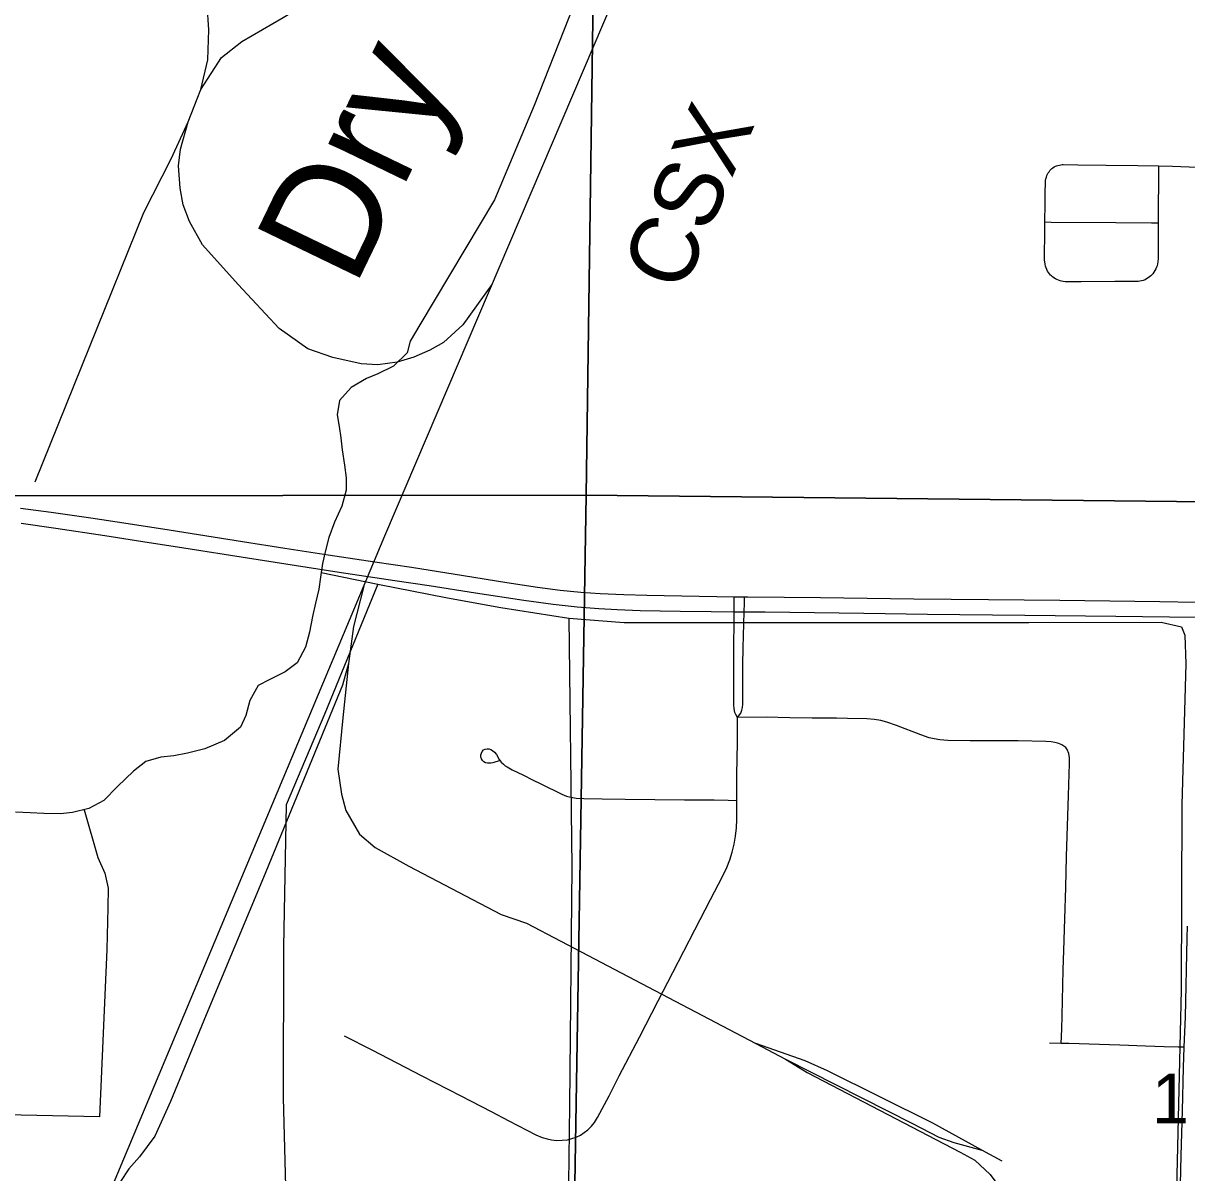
# Model space of a CAD drawing. Extents: x 0 to 34, y 0 to 22.
# Drawn here: x 7.043 to 8.019, y 17.308 to 18.272 of the extents above; entities that cross this region are included whole.
import ezdxf

# ---------------------------------------------------------------- set-up
doc = ezdxf.new("R2010")
doc.units = 0
for name, color, linetype in [('GM_X_Corporation', 7, 'Continuous'), ('GM_X_County_Road', 7, 'Continuous'), ('GM_X_Minor_River', 7, 'Continuous'), ('GM_X_Minor_River_Text', 7, 'Continuous'), ('GM_X_Rail_Line', 7, 'Continuous'), ('GM_X_Rail_Line_Text', 7, 'Continuous'), ('GM_X_Section_Text', 7, 'Continuous'), ('GM_X_State_Route', 7, 'Continuous'), ('GM_X_Township_Road', 7, 'Continuous')]:
    doc.layers.add(name, color=color, linetype=linetype)

msp = doc.modelspace()

# ---------------------------------------------------------------- linework, layer by layer
at = {"layer": 'GM_X_Corporation'}
for points in [[(6.50454, 18.87812), (7.00649, 18.89081), (7.52848, 18.83427), (7.51498, 17.8763), (6.49696, 17.87536)], [(7.52848, 18.83427), (8.56457, 18.82324), (8.56257, 18.42645), (8.55788, 17.86518), (7.51498, 17.8763)], [(6.49696, 17.87536), (7.51498, 17.8763), (7.49907, 16.90775), (6.47447, 16.92623)], [(7.51498, 17.8763), (8.55788, 17.86518), (8.55531, 17.77577), (8.50493, 17.42275), (8.49555, 16.88277), (7.49907, 16.90775)]]:
    msp.add_lwpolyline(points, close=True, dxfattribs=at)
at = {"layer": 'GM_X_County_Road'}
for points in [[(8.01675, 17.41339), (8.0177, 17.43885), (8.01916, 17.50487), (8.01949, 17.51487)], [(8.01278, 17.26906), (8.01322, 17.28589), (8.01417, 17.3225), (8.01539, 17.36001), (8.01612, 17.39628), (8.01675, 17.41339)]]:
    msp.add_lwpolyline(points, dxfattribs=at)
at = {"layer": 'GM_X_Minor_River'}
for points in [[(7.54054, 18.37809), (7.50431, 18.28675), (7.4715, 18.20327), (7.43799, 18.12398), (7.37544, 18.01924)], [(7.37544, 18.01924), (7.36733, 18.00567), (7.36494, 17.99583), (7.35346, 17.98459), (7.34015, 17.9783), (7.33066, 17.97425), (7.31772, 17.96682), (7.30813, 17.95593), (7.30609, 17.94381), (7.30785, 17.93392), (7.30924, 17.92441), (7.31024, 17.91453), (7.31235, 17.90159), (7.31372, 17.89095), (7.31359, 17.8807), (7.31001, 17.86708), (7.3038, 17.85387), (7.2991, 17.84102), (7.29592, 17.82892), (7.2939, 17.81907), (7.29225, 17.8077), (7.2906, 17.79748), (7.28781, 17.78574), (7.2854, 17.77477), (7.28296, 17.76151), (7.2794, 17.74903), (7.27243, 17.73583), (7.26251, 17.72836), (7.24958, 17.72169), (7.2397, 17.71688), (7.23273, 17.70406), (7.22955, 17.69158), (7.22489, 17.68176), (7.21152, 17.67054), (7.19519, 17.66354), (7.18041, 17.65993), (7.16905, 17.65779), (7.15808, 17.65679), (7.14557, 17.65315), (7.13526, 17.64493), (7.12188, 17.63219), (7.11039, 17.62019), (7.09784, 17.61351), (7.08419, 17.61027), (7.07398, 17.60926), (7.06001, 17.60943), (7.04868, 17.60996), (7.03622, 17.61049)], [(7.2928, 17.81154), (7.34015, 17.80179), (7.39855, 17.79043), (7.4434, 17.78227), (7.50033, 17.7732), (7.54675, 17.76959), (7.64421, 17.7695), (7.75679, 17.7696), (7.88636, 17.76949), (7.99744, 17.77), (8.01438, 17.76599), (8.01732, 17.75912), (8.01814, 17.73481), (8.01473, 17.61679), (8.01424, 17.46153), (8.0102, 17.29417), (8.00744, 17.10934), (7.99612, 16.90563), (7.99002, 16.78462)], [(7.34015, 17.80179), (7.29568, 17.6934), (7.26334, 17.61675), (7.26105, 17.49758), (7.26093, 17.3708), (7.26444, 17.23296)], [(7.50033, 17.7732), (7.50294, 17.56477), (7.50111, 17.36436), (7.4983, 17.1465), (7.49753, 16.99885)], [(7.09397, 17.61259), (7.10524, 17.57242), (7.11112, 17.55944), (7.11398, 17.54688), (7.11377, 17.53056), (7.11293, 17.49527), (7.10659, 17.3549), (6.98801, 17.35752), (6.98647, 17.23873), (6.98545, 17.0721), (6.98596, 16.9066), (6.98102, 16.72902), (6.9765, 16.58447), (6.96643, 16.36141)]]:
    msp.add_lwpolyline(points, dxfattribs=at)
at = {"layer": 'GM_X_Rail_Line'}
for p, q in [((7.65732, 17.4165), (7.68214, 17.40332)), ((7.86393, 17.3177), (7.84679, 17.32712))]:
    msp.add_line(p, q, dxfattribs=at)
for points in [[(7.19183, 18.21678), (7.19765, 18.24147), (7.19852, 18.26676), (7.19707, 18.28799), (7.19067, 18.30427), (7.17206, 18.33567), (7.16479, 18.35224), (7.15927, 18.37405), (7.1584, 18.39062), (7.15956, 18.4069), (7.16305, 18.41998), (7.1898, 18.48773), (7.30345, 18.7703), (7.71605, 19.7423), (7.73668, 19.78564), (7.75221, 19.80327), (7.77065, 19.81832), (7.78813, 19.82778), (7.80537, 19.83531), (7.8226, 19.83919), (7.85149, 19.8421), (7.89227, 19.84235), (7.93353, 19.84041), (7.9913, 19.8421)], [(5.77239, 14.1), (5.90233, 14.40655), (6.10798, 14.90116), (7.0925, 17.23709), (7.34619, 17.84225), (7.58257, 18.39702), (7.87412, 19.10843), (7.90221, 19.17079), (7.93383, 19.23755), (7.95841, 19.28147), (7.99266, 19.31836), (8.05237, 19.36024), (8.34578, 19.53684)], [(7.19183, 18.21678), (7.20904, 18.2434), (7.22605, 18.25694), (7.26075, 18.27707), (7.31351, 18.309), (7.35828, 18.33676), (7.3791, 18.35377), (7.39319, 18.37303), (7.42929, 18.44836), (7.72615, 19.20856)], [(7.18103, 18.18951), (7.18877, 18.20881), (7.19183, 18.21678)], [(7.05287, 17.8875), (7.14404, 18.11338), (7.16683, 18.15854), (7.18103, 18.18951)], [(7.43597, 18.05297), (7.41163, 18.01917), (7.39527, 18.00432), (7.38376, 17.99796), (7.37043, 17.99221), (7.35649, 17.98796), (7.34013, 17.98584), (7.3262, 17.98645), (7.30257, 17.9919), (7.28136, 17.99917), (7.25732, 18.01621), (7.22296, 18.05296), (7.19314, 18.08625), (7.1821, 18.10586), (7.17694, 18.12005), (7.17436, 18.13381), (7.17307, 18.15252), (7.17458, 18.16671), (7.18103, 18.18951)], [(7.32855, 17.80017), (7.31988, 17.76617), (7.31551, 17.73521)], [(7.31551, 17.73521), (7.31068, 17.71715), (7.24438, 17.55579), (7.19619, 17.44059), (7.16636, 17.36786), (7.15308, 17.33884), (7.14024, 17.32149), (7.13118, 17.31146), (7.12428, 17.30079), (7.11054, 17.28011)], [(7.31551, 17.73521), (7.31097, 17.68951), (7.30677, 17.64657), (7.30961, 17.62566), (7.31346, 17.6118), (7.32494, 17.59201), (7.33806, 17.5808), (7.36624, 17.56512), (7.44374, 17.52461), (7.46493, 17.5173), (7.49373, 17.50223), (7.65732, 17.4165)], [(7.84679, 17.32712), (7.80574, 17.34969), (7.71747, 17.3937), (7.69877, 17.4019), (7.65732, 17.4165)], [(7.68214, 17.40332), (7.7005, 17.39205), (7.82888, 17.32547), (7.84113, 17.31857), (7.85394, 17.30676), (7.86335, 17.29375), (7.87061, 17.28169), (7.87477, 17.26844), (7.87584, 17.2543), (7.87444, 17.24019), (7.8712, 17.2261), (7.8655, 17.21266), (7.85541, 17.19312)], [(7.68214, 17.40332), (7.78884, 17.34945), (7.8109, 17.3379), (7.82343, 17.33358), (7.84679, 17.32712)]]:
    msp.add_lwpolyline(points, dxfattribs=at)
at = {"layer": 'GM_X_State_Route'}
for points in [[(7.04037, 17.86552), (7.06626, 17.86218), (7.09948, 17.85739), (7.13083, 17.85265), (7.16521, 17.8472), (7.22659, 17.83752), (7.26221, 17.832), (7.29847, 17.82644), (7.33782, 17.82055), (7.36855, 17.81589), (7.41215, 17.809), (7.44836, 17.80322), (7.47416, 17.79927), (7.4933, 17.79679), (7.51064, 17.7951), (7.52678, 17.79396), (7.54667, 17.79303), (7.56595, 17.79247), (7.63915, 17.79124), (7.64781, 17.7911), (7.65051, 17.79105), (7.71144, 17.79057), (7.78977, 17.78953), (7.85257, 17.78894), (7.91226, 17.7884), (7.99618, 17.78735), (8.02679, 17.78677)], [(7.04104, 17.85282), (7.06999, 17.84877), (7.11118, 17.84248), (7.14312, 17.83749), (7.17752, 17.8322), (7.23094, 17.82392), (7.27208, 17.81745), (7.30771, 17.81192), (7.35444, 17.80497), (7.38333, 17.80051), (7.42201, 17.79437), (7.46257, 17.78835), (7.48719, 17.78509), (7.50755, 17.78281), (7.52548, 17.78128), (7.54097, 17.78042), (7.56022, 17.7798), (7.59378, 17.77911), (7.61988, 17.77877), (7.63908, 17.77864), (7.64751, 17.77857), (7.66527, 17.77845), (7.74796, 17.7773), (7.80143, 17.77659), (7.88288, 17.77565), (7.95935, 17.77485), (8.02662, 17.77409)]]:
    msp.add_lwpolyline(points, dxfattribs=at)
at = {"layer": 'GM_X_Township_Road'}
for p, q in [((7.99503, 18.15257), (7.99486, 18.10472)), ((7.91357, 17.41659), (7.90369, 17.41685))]:
    msp.add_line(p, q, dxfattribs=at)
for points in [[(7.89988, 18.10553), (7.90004, 18.12074), (7.90006, 18.12947), (7.90022, 18.13908), (7.90037, 18.14035), (7.90067, 18.14176), (7.90105, 18.14318), (7.90148, 18.14454), (7.90198, 18.14568), (7.90256, 18.14667), (7.90327, 18.14772), (7.9041, 18.14871), (7.90494, 18.14963), (7.90571, 18.15037), (7.90648, 18.15096), (7.90774, 18.15176), (7.90866, 18.15222), (7.90965, 18.15259), (7.91067, 18.15294), (7.91194, 18.15324), (7.91308, 18.15349), (7.91419, 18.15365), (7.91521, 18.15374), (7.92755, 18.15345), (7.95115, 18.15307), (7.97788, 18.15298), (7.99503, 18.15257)], [(7.99503, 18.15257), (8.00701, 18.15228), (8.0419, 18.15097)], [(7.99486, 18.10472), (7.99485, 18.10192), (7.99475, 18.0895), (7.99475, 18.07769), (7.99472, 18.07501), (7.99452, 18.07213), (7.99423, 18.0704), (7.9939, 18.06888), (7.99349, 18.06768), (7.99287, 18.06629), (7.99218, 18.06485), (7.99127, 18.06337), (7.99032, 18.06209), (7.98946, 18.0611), (7.98876, 18.0604), (7.9877, 18.0595), (7.98646, 18.05859), (7.98514, 18.05777), (7.98383, 18.05712), (7.98239, 18.05646), (7.98087, 18.05604), (7.97951, 18.05584), (7.97819, 18.05575), (7.97641, 18.05575), (7.95845, 18.05556), (7.93028, 18.05536), (7.91683, 18.05532), (7.9151, 18.05548), (7.91366, 18.05581), (7.91251, 18.05622), (7.91124, 18.05671), (7.90996, 18.05729), (7.90868, 18.05795), (7.90736, 18.05872), (7.90634, 18.05946), (7.9054, 18.06029), (7.90465, 18.06095), (7.90379, 18.06202), (7.90292, 18.06317), (7.90214, 18.06436), (7.90149, 18.06555), (7.90087, 18.06699), (7.90037, 18.06855), (7.9, 18.0702), (7.89971, 18.07205), (7.89962, 18.07362), (7.89944, 18.081), (7.89973, 18.09215), (7.89988, 18.10553)], [(7.89988, 18.10553), (7.90497, 18.10548), (7.95937, 18.10499), (7.98922, 18.10477), (7.99486, 18.10472)], [(7.64197, 17.69004), (7.64041, 17.69253), (7.63978, 17.69425), (7.63916, 17.69721), (7.639, 17.70063), (7.6388, 17.70748), (7.63897, 17.72808), (7.63891, 17.7504), (7.63903, 17.76943), (7.63908, 17.77864), (7.63913, 17.78625), (7.63915, 17.79124)], [(7.64751, 17.77857), (7.64769, 17.78578), (7.64781, 17.7911)], [(7.64629, 17.70119), (7.64645, 17.70484), (7.64637, 17.71357), (7.64648, 17.73413), (7.64677, 17.74846), (7.64751, 17.77857)], [(7.64197, 17.69004), (7.64461, 17.69363), (7.6457, 17.69596), (7.64617, 17.69845), (7.64629, 17.70119)], [(7.64179, 17.65949), (7.64188, 17.66463), (7.64187, 17.67337), (7.64197, 17.69004)], [(7.91357, 17.41659), (7.91391, 17.42861), (7.91424, 17.43979), (7.91508, 17.47832), (7.91569, 17.49445), (7.91659, 17.52117), (7.91737, 17.54726), (7.91802, 17.57335), (7.91968, 17.62439), (7.92056, 17.65132), (7.9204, 17.65615), (7.91977, 17.65972), (7.91851, 17.66307), (7.91732, 17.66468), (7.9158, 17.66598), (7.91405, 17.66703), (7.91147, 17.6681), (7.90813, 17.66903), (7.90496, 17.66959), (7.90055, 17.6699), (7.87752, 17.67041), (7.84331, 17.67034), (7.8371, 17.67047), (7.8185, 17.67077), (7.81175, 17.67124), (7.80693, 17.67197), (7.80278, 17.67298), (7.79579, 17.67535), (7.77547, 17.68313), (7.7672, 17.68603), (7.76232, 17.68728), (7.75674, 17.68826), (7.75048, 17.68879), (7.73427, 17.68907), (7.72497, 17.68935), (7.70445, 17.68948), (7.68582, 17.68976), (7.66591, 17.69007), (7.64197, 17.69004)], [(7.44241, 17.65347), (7.43926, 17.65266), (7.43659, 17.65203), (7.43501, 17.65171), (7.43343, 17.65153), (7.4323, 17.65158), (7.43066, 17.65199), (7.42923, 17.65285), (7.42802, 17.65398), (7.42716, 17.65533), (7.42674, 17.65683), (7.42675, 17.65849), (7.42712, 17.6601), (7.42785, 17.66153), (7.42892, 17.66267), (7.43028, 17.66342), (7.43182, 17.66376), (7.43343, 17.66365), (7.43501, 17.6631), (7.43648, 17.66226), (7.43822, 17.66076), (7.43967, 17.65897), (7.4421, 17.65467), (7.44362, 17.65251), (7.4455, 17.65066), (7.44711, 17.64932), (7.44859, 17.64841), (7.45297, 17.64602), (7.46172, 17.64172), (7.47065, 17.63733), (7.47708, 17.63417), (7.49445, 17.62571), (7.49857, 17.62405), (7.50225, 17.623), (7.50665, 17.62228), (7.51293, 17.62186), (7.52851, 17.62168), (7.54778, 17.6215), (7.59753, 17.62076), (7.62241, 17.62081), (7.63419, 17.62058), (7.64132, 17.62045)], [(7.64132, 17.62045), (7.64138, 17.6379), (7.64179, 17.65949)], [(7.31195, 17.423), (7.33523, 17.41115), (7.37719, 17.3894), (7.40986, 17.3727), (7.43527, 17.35957), (7.45009, 17.35169), (7.47278, 17.33996), (7.47802, 17.33776), (7.48227, 17.33643), (7.48602, 17.33569), (7.49045, 17.33528), (7.49491, 17.33531), (7.49934, 17.33583), (7.50308, 17.3367), (7.50669, 17.33799), (7.51013, 17.33968), (7.51337, 17.34173), (7.51638, 17.34409), (7.51957, 17.34721), (7.52197, 17.35021), (7.52463, 17.35453), (7.53423, 17.37271), (7.54281, 17.38928), (7.55962, 17.4219), (7.57539, 17.45224), (7.5878, 17.47593), (7.60622, 17.51192), (7.61942, 17.53729), (7.62943, 17.55665), (7.63288, 17.56401), (7.63539, 17.57044), (7.63753, 17.57701), (7.63912, 17.58372), (7.6403, 17.59053), (7.64106, 17.59741), (7.64139, 17.6043), (7.64132, 17.62045)], [(8.01675, 17.41339), (8.01172, 17.41349), (7.99975, 17.41372), (7.98425, 17.41424), (7.96257, 17.41502), (7.91982, 17.41642), (7.91357, 17.41659)]]:
    msp.add_lwpolyline(points, dxfattribs=at)

# ---------------------------------------------------------------- texts
at = {"layer": 'GM_X_Minor_River_Text'}
msp.add_text('Dry', height=0.094773, rotation=64.20639, dxfattribs=at).set_placement((7.32059, 18.0494))
at = {"layer": 'GM_X_Rail_Line_Text'}
msp.add_text('CSX', height=0.056629, rotation=66.87129, dxfattribs=at).set_placement((7.59565, 18.04455))
at = {"layer": 'GM_X_Section_Text'}
msp.add_text('1', height=0.04186, rotation=0.00001, dxfattribs=at).set_placement((7.98957, 17.34946))

doc.saveas('drawing.dxf')
